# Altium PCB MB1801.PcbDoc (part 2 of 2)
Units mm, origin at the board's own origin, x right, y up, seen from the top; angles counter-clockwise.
Board outline 70.1 x 57.1 mm, 2 copper layers (Top Layer, Bottom Layer), stack 1.554 mm thick; 124 components, 115 nets, 557 pads, 485 vias.
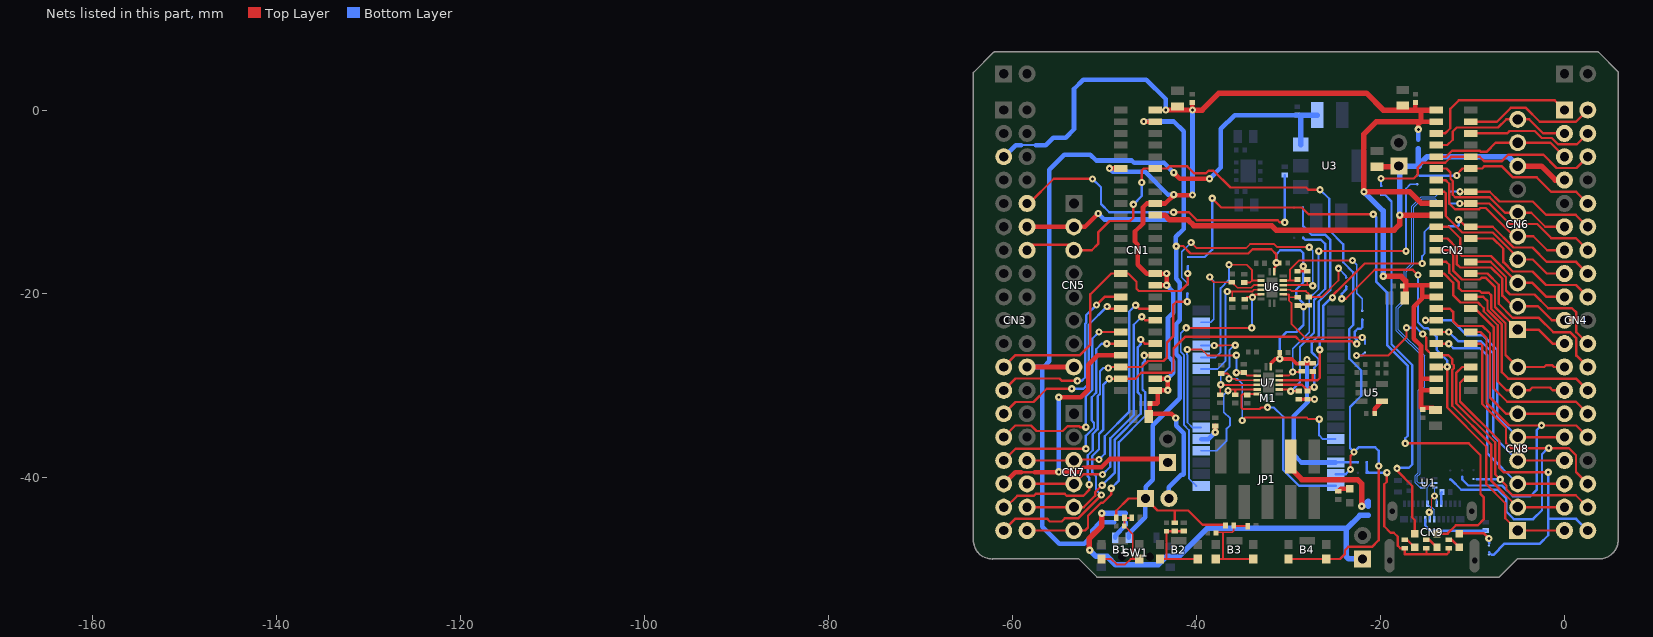
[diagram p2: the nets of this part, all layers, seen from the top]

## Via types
v1: diameter 0.8, hole 0.3, Top Layer to Bottom Layer, tented both sides, 485 vias

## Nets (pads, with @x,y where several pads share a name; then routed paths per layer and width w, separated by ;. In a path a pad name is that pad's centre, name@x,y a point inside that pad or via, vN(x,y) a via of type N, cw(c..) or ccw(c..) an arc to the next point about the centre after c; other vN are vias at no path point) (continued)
GPIO14: CN1.29 CN3.23 SB10.1 | length 31.1
  Top Layer w0.254: CN3.23@-60.96,-27.94 -59.67,-26.65 -52.68,-26.65 -51.537,-25.507 -51.537,-20.041 -49.276,-17.78 CN1.29@-48.225,-17.78 -47.422,-17.78 -46.533,-18.669 -46.533,-19.437 -46.285,-19.685 -41.732,-19.685 -40.97,-18.923 v1(-40.97,-17.78) v1@-40.97,-17.653
  Bottom Layer w0.254: v1(-40.97,-17.78) -40.97,-17.002 SB10.1@-40.931,-16.963
GPIO15/OSC32_IN: CN1.33 CN3.25 | length 21.1
  Top Layer w0.254: CN3.25@-60.96,-30.48 -59.665,-29.185 -54.89,-29.185 -54.625,-29.45 v1(-52.95,-29.45) ; v1(-50.88,-21.2) -50,-20.32 CN1.33@-48.225,-20.32
  Bottom Layer w0.254: v1(-52.95,-29.45) -52.49,-29.45 -52.104,-29.064 -52.104,-23.239 -52,-23.135 -52,-22.32 v1(-50.88,-21.2)
GPIO16/OSC32_OUT: CN1.35 CN3.27 | length 21.4
  Top Layer w0.254: CN3.27@-60.96,-33.02 -59.69,-31.75 -57.725,-31.75 -56.275,-30.3 v1(-53.575,-30.3) ; v1(-49.725,-21.361) -49.496,-21.59 CN1.35@-48.225,-21.59
  Bottom Layer w0.254: v1(-53.575,-30.3) -52.3,-30.3 -51.714,-29.714 -51.714,-23.35 v1(-49.725,-21.361)
GPIO17: CN1.36 CN3.32 CN7.3 | length 28.6
  Top Layer w0.254: CN3.32@-58.42,-38.1 CN7.3@-53.34,-38.1 -53.24,-38 v1(-50.6,-38) ; v1(-46.625,-21.225) -46.6,-21.225 -46.235,-21.59 CN1.36@-44.485,-21.59
  Bottom Layer w0.254: v1(-50.6,-38) -49.975,-37.375 -49.975,-35.475 -47.325,-32.825 -47.325,-21.925 v1(-46.625,-21.225)
GPIO18: CN1.38 CN3.34 CN7.4 | length 29.3
  Top Layer w0.254: CN3.34@-58.42,-40.64 CN7.4@-53.34,-40.64 -52.299,-39.599 -50.436,-39.599 -50.339,-39.501 -50.22,-39.383 v1@-50.183,-39.383 ; v1(-45.95,-22.475) -45.565,-22.86 CN1.38@-44.485,-22.86
  Bottom Layer w0.254: v1(-50.216,-39.624) -49.375,-38.783 -49.375,-35.7 -46.825,-33.15 -46.825,-23.35 v1(-45.95,-22.475)
GPIO19/OSC_IN: CN1.39 CN3.29 | length 23.3
  Top Layer w0.254: CN3.29@-60.96,-35.56 -59.7,-34.3 -57.981,-34.3 -57.382,-34.9 -54.534,-34.9 -54,-34.366 -52.759,-34.366 -52.65,-34.475 v1(-52.025,-34.475) ; v1(-50.605,-24.13) CN1.39@-48.225,-24.13
  Bottom Layer w0.254: v1(-52.025,-34.475) -52.025,-31.125 -51.333,-30.433 -51.333,-24.858 v1(-50.605,-24.13)
GPIO20/OSC_OUT: CN1.41 CN3.31 | length 23.9
  Top Layer w0.254: CN3.31@-60.96,-38.1 -59.685,-36.825 v1(-52.025,-36.825) ; v1(-49.75,-25.4) CN1.41@-48.225,-25.4
  Bottom Layer w0.254: v1(-52.025,-36.825) -52.025,-35.412 -51.148,-34.535 -51.148,-34.015 -51.4,-33.763 -51.4,-31.225 -50.902,-30.727 -50.902,-26.002 -50.3,-25.4 v1(-49.75,-25.4)
GPIO21: CN1.42 CN3.36 CN7.5 | length 29
  Top Layer w0.254: CN3.36@-58.42,-43.18 CN7.5@-53.34,-43.18 -52.273,-43.18 -51.029,-41.935 -51.029,-41.554 v1(-50.267,-40.792) ; v1(-46.075,-24.95) -45.625,-25.4 CN1.42@-44.485,-25.4
  Bottom Layer w0.254: v1(-50.267,-40.792) -48.875,-39.401 -48.875,-35.825 -46.075,-33.025 -46.075,-31.006 -46.375,-30.706 -46.375,-25.8 -46.075,-25.5 v1(-46.075,-24.95)
GPIO22: CN1.44 CN3.38 CN7.6 | length 29.7
  Top Layer w0.254: CN3.38@-58.42,-45.72 CN7.6@-53.34,-45.72 -52.121,-45.72 -51.791,-45.39 -51.791,-44.105 -50.383,-42.697 -50.165,-42.697 -49.276,-41.808 v1(-49.276,-41.123) ; v1(-45.675,-26.675) -45.68,-26.67 CN1.44@-44.485,-26.67
  Bottom Layer w0.254: v1(-49.276,-41.123) -48.438,-40.284 -48.438,-36.113 -45.575,-33.25 -45.575,-30.675 -45.875,-30.375 -45.875,-27.55 -45.625,-27.3 -45.625,-26.675 v1(-45.675,-26.675)
GPIO23: CN1.45 CN3.35 SB5.1 | length 40.6
  Top Layer w0.254: CN3.35@-60.96,-43.18 -60.73,-43.18 -59.5,-41.95 -57.706,-41.95 -57.488,-41.732 -54.337,-41.732 -54.119,-41.95 -52.325,-41.95 -51.675,-41.3 v1(-51.675,-40.725) ; v1(-49.6,-28.05) -49.575,-28.05 -49.465,-27.94 CN1.45@-48.225,-27.94 -45.949,-27.94 -45.288,-27.28 -43.586,-27.28 -43.205,-26.899 -43.205,-25.273 -42.545,-24.613 -42.545,-21.184 -42.215,-20.853 -41.275,-20.853 -40.996,-20.574 v1(-40.996,-20.828)
  Bottom Layer w0.254: v1(-51.675,-40.725) -51.675,-39.95 -51.825,-39.8 -51.825,-37.525 -51.283,-36.982 -51.283,-35.229 -50.75,-34.696 -50.75,-31.125 -50.495,-30.87 -50.495,-28.395 -50.15,-28.05 v1(-49.6,-28.05) ; v1(-40.996,-20.828) -40.996,-19.982 SB5.1@-40.979,-19.966
GPIO24: CN1.47 CN3.37 SB3.1 | length 60.1
  Top Layer w0.254: CN3.37@-60.96,-45.72 -59.665,-44.425 -56.261,-44.425 -55.956,-44.729 -54.661,-44.729 -54.331,-44.399 -52.883,-44.399 v1(-50.343,-41.859) ; v1@-49.525,-29.21 v1(-49.493,-29.21) CN1.47@-48.225,-29.21 -46.634,-29.21 -45.999,-28.575 -42.748,-28.575 -42.494,-28.321 -42.494,-25.933 -41.199,-24.638 -29.235,-24.638 -28.727,-25.146 -23.114,-25.146 -22.835,-25.425 v1(-22.581,-25.425)
  Bottom Layer w0.254: v1@-50.341,-41.859 v1(-50.343,-41.859) -50.343,-41.857 -50.925,-41.275 -50.925,-39.825 -51.35,-39.4 -51.35,-37.634 -50.595,-36.879 -50.595,-35.22 -50.125,-34.75 -50.125,-29.842 v1(-49.493,-29.21) ; v1(-22.581,-25.425) -22.581,-24.994 -22.784,-24.79 -22.784,-24.079 -22.479,-23.774 -22.149,-23.774 -21.98,-23.606 SB3.1@-21.98,-22.8
GPIO25: CN2.4 CN4.2 | length 14.5
  Top Layer w0.254: CN2.4@-10.195,-1.27 -7.341,-1.27 -5.842,0.229 -4.191,0.229 -2.687,-1.275 1.265,-1.275 CN4.2@2.54,0
GPIO26: CN2.5 CN4.1 | length 17.1
  Top Layer w0.254: CN2.5@-13.935,-2.54 -12.99,-2.54 -12.425,-1.975 -12.425,0.125 -11.5,1.05 -1.05,1.05 CN4.1@0,0
GPIO27: CN2.6 CN4.4 | length 13.9
  Top Layer w0.254: CN2.6@-10.195,-2.54 -6.223,-2.54 -5.958,-2.275 -3.237,-2.275 -2.462,-3.05 -1.375,-3.05 -0.7,-3.725 1.355,-3.725 CN4.4@2.54,-2.54
GPIO28: CN2.7 CN4.3 CN6.10 | length 16.2
  Top Layer w0.254: CN2.7@-13.935,-3.81 -12.735,-3.81 -12.15,-3.225 -12.15,-2.35 -11.7,-1.9 -7.209,-1.9 -6.325,-1.016 CN6.10@-5.08,-1.016 -3.835,-1.016 -2.311,-2.54 CN4.3@0,-2.54
GPIO29: CN2.9 CN4.5 CN6.9 | length 15.3
  Top Layer w0.254: CN2.9@-13.935,-5.08 -12.883,-5.08 -12.228,-4.425 -9.2,-4.425 -9.075,-4.55 -8.475,-4.55 -7.481,-3.556 CN6.9@-5.08,-3.556 -1.524,-3.556 CN4.5@0,-5.08
GPIO30: CN2.10 CN4.6 SB9.1 | length 26.3
  Top Layer w0.254: v1(-19.939,-7.442) -16.383,-7.442 -15.951,-7.01 -15.951,-6.248 -15.443,-5.74 -12.954,-5.74 -12.294,-5.08 CN2.10@-10.195,-5.08 -9.198,-5.08 -8.69,-5.588 -6.858,-5.588 -6.12,-4.85 -2.3,-4.85 -0.85,-6.3 1.32,-6.3 CN4.6@2.54,-5.08
  Bottom Layer w0.254: v1(-19.939,-7.442) -19.939,-8.255 SB9.1@-19.932,-8.262
GPIO31: CN2.11 CN4.11 CN6.6 | length 17.8
  Top Layer w0.254: CN2.11@-13.935,-6.35 -12.839,-6.35 -12.382,-6.807 -12.382,-7.481 -12.142,-7.721 -12.142,-9.219 -11.861,-9.5 -8.128,-9.5 -6.452,-11.176 CN6.6@-5.08,-11.176 -3.607,-11.176 -2.083,-12.7 CN4.11@0,-12.7
GPIO32: CN2.12 CN4.10 SB12.1 | length 20.5
  Top Layer w0.254: v1(-11.709,-7.112) -11.709,-6.985 -11.074,-6.35 CN2.12@-10.195,-6.35 -8.944,-6.35 -8.69,-6.096 -6.833,-6.096 -5.604,-7.325 -3,-7.325 -1.425,-8.9 1.28,-8.9 CN4.10@2.54,-10.16
  Bottom Layer w0.254: -15.748,-7.163 -11.76,-7.163 v1(-11.709,-7.112)
GPIO33: CN2.13 CN4.13 CN6.5 | length 18.5
  Top Layer w0.254: CN2.13@-13.935,-7.62 -12.929,-7.62 -12.522,-8.026 -12.522,-10.16 -11.882,-10.8 -9.3,-10.8 -9.15,-10.65 -8.55,-10.65 -5.484,-13.716 CN6.5@-5.08,-13.716 -3.384,-13.716 -1.86,-15.24 CN4.13@0,-15.24
GPIO34: CN2.15 CN4.15 CN6.4 | length 19.2
  Top Layer w0.254: CN2.15@-13.935,-8.89 -13.06,-8.89 -12.903,-9.047 -12.903,-11.522 -11.1,-13.325 -7.8,-13.325 -5.08,-16.045 CN6.4@-5.08,-16.256 -3.444,-16.256 -1.92,-17.78 CN4.15@0,-17.78
GPIO35: CN2.16 CN4.12 SB16.1 | length 16.6
  Top Layer w0.2: v1@-11.354,-8.873 -11.354,-8.89 CN2.16@-10.195,-8.89
  Top Layer w0.254: CN2.16@-10.195,-8.89 -8.128,-8.89 -7.068,-9.95 -3.436,-9.95 -1.986,-11.4 1.24,-11.4 CN4.12@2.54,-12.7
  Bottom Layer w0.2: SB16.1@-12.51,-8.87 v1(-11.354,-8.87)
GPIO36: CN2.18 CN4.14 SB14.1 | length 17.1
  Top Layer w0.254: v1(-11.379,-10.16) CN2.18@-10.195,-10.16 -8.18,-10.16 -5.94,-12.4 -2.967,-12.4 -1.442,-13.925 1.225,-13.925 CN4.14@2.54,-15.24
  Bottom Layer w0.254: SB14.1@-12.453,-10.16 v1(-11.379,-10.16)
GPIO37: CN2.21 CN4.17 CN6.3 | length 18.1
  Top Layer w0.254: CN2.21@-13.935,-12.7 -12.575,-12.7 -11.325,-13.95 -11.325,-15.7 -11.15,-15.875 -8,-15.875 -5.08,-18.795 -3.479,-18.796 -1.955,-20.32 CN4.17@0,-20.32
GPIO38: CN2.22 CN4.16 SB13.1 | length 18.2
  Top Layer w0.254: v1(-11.506,-11.913) -10.719,-12.7 CN2.22@-10.195,-12.7 -7.8,-12.7 -5.55,-14.95 -3.475,-14.95 -1.915,-16.51 1.27,-16.51 CN4.16@2.54,-17.78
  Bottom Layer w0.254: SB13.1@-12.555,-12.624 -11.608,-12.624 -11.506,-12.522 v1(-11.506,-11.913)
GPIO39: CN2.23 CN4.19 CN6.2 | length 19.7
  Top Layer w0.254: CN2.23@-13.935,-13.97 -12.73,-13.97 -11.725,-14.975 -11.725,-16.725 -11.325,-17.125 -7.975,-17.125 -6.75,-18.35 -6.75,-20.175 -5.589,-21.336 CN6.2@-5.08,-21.336 -2.889,-21.336 -1.365,-22.86 CN4.19@0,-22.86
GPIO40: CN2.24 CN4.18 | length 16.2
  Top Layer w0.254: CN2.24@-10.195,-13.97 -7.755,-13.97 -6.64,-15.085 -6.64,-16.535 -5.625,-17.55 -3.475,-17.55 -2,-19.025 1.245,-19.025 CN4.18@2.54,-20.32
GPIO41: CN2.25 CN4.21 CN6.1 | length 20.6
  Top Layer w0.254: CN2.25@-13.935,-15.24 -12.56,-15.24 -12.1,-15.7 -12.1,-17.45 -11.125,-18.425 -9.206,-18.425 -9.204,-18.423 -9.198,-18.423 -9.025,-18.25 -8.53,-18.25 -7.55,-19.23 -7.55,-21.406 CN6.1@-5.08,-23.876 -2.824,-23.876 -1.3,-25.4 CN4.21@0,-25.4
GPIO42: CN2.27 CN4.23 CN8.8 | length 22.6
  Top Layer w0.254: CN2.27@-13.935,-16.51 -12.84,-16.51 -12.525,-16.825 -12.525,-17.7 -11.475,-18.75 -11.475,-19.375 -11.175,-19.675 -9.206,-19.675 -9.018,-19.863 -8.237,-19.863 -7.975,-20.125 -7.975,-21.6 -6.4,-23.175 -6.4,-26.62 CN8.8@-5.08,-27.94 -2.184,-27.94 -1.981,-27.737 -1.346,-27.737 -1.143,-27.94 CN4.23@0,-27.94
GPIO43: CN2.28 CN4.22 | length 18.5
  Top Layer w0.254: CN2.28@-10.195,-16.51 -8.015,-16.51 -6.345,-18.18 -6.345,-19.63 -5.925,-20.05 -3.25,-20.05 -1.75,-21.55 0.825,-21.55 1.3,-22.025 1.3,-24.16 CN4.22@2.54,-25.4
GPIO44: CN2.29 CN4.25 CN8.7 | length 24
  Top Layer w0.254: CN2.29@-13.935,-17.78 -13.095,-17.78 -12.1,-18.775 -12.1,-20.117 -11.292,-20.925 -9.394,-20.925 -8.775,-21.544 -8.775,-21.88 -7.25,-23.405 -7.25,-29.5 -6.27,-30.48 CN8.7@-5.08,-30.48 -3.81,-30.48 -3.505,-30.175 -1.575,-30.175 -1.27,-30.48 CN4.25@0,-30.48
GPIO45: CN2.30 CN4.24 | length 19.2
  Top Layer w0.254: CN2.30@-10.195,-17.78 -8.37,-17.78 -7.15,-19 -7.15,-21.064 -5.614,-22.6 -2.775,-22.6 -1.225,-24.15 0.6,-24.15 1.3,-24.85 1.3,-26.7 CN4.24@2.54,-27.94
GPIO46: CN2.34 CN4.26 | length 20.5
  Top Layer w0.254: CN2.34@-10.195,-20.32 -8.83,-20.32 -8.37,-20.78 -8.37,-21.74 -6.8,-23.31 -6.8,-28.5 -6.1,-29.2 1.26,-29.2 CN4.26@2.54,-30.48
GPIO47: CN2.35 CN4.27 CN8.6 | length 23.3
  Top Layer w0.254: CN2.35@-13.935,-21.59 -12.46,-21.59 -12.1,-21.95 -12.1,-22.95 -11.575,-23.475 -8.9,-23.475 -8.1,-24.275 -8.1,-31.265 -6.345,-33.02 CN8.6@-5.08,-33.02 CN4.27@0,-33.02
GPIO48: CN2.36 CN4.28 | length 21.4
  Top Layer w0.254: CN2.36@-10.195,-21.59 -9.71,-21.59 -7.7,-23.6 -7.7,-30.25 -6.225,-31.725 1.245,-31.725 CN4.28@2.54,-33.02
GPIO49: CN2.37 CN4.29 CN8.5 | length 25.8
  Top Layer w0.254: v1(-15.1,-22.85) -15.09,-22.86 CN2.37@-13.935,-22.86 ; CN8.5@-5.08,-35.56 CN4.29@0,-35.56
  Bottom Layer w0.254: v1(-15.1,-22.85) -12.275,-22.85 -10.65,-24.475 -8.9,-24.475 -7.3,-26.075 -7.3,-33.34 CN8.5@-5.08,-35.56
GPIO50: CN2.39 CN4.31 CN8.4 | length 25
  Top Layer w0.254: CN2.39@-13.935,-24.13 v1(-12.57,-24.13) v1@-12.53,-24.13 ; CN8.4@-5.08,-38.1 CN4.31@0,-38.1
  Bottom Layer w0.254: v1(-12.57,-24.13) -11.575,-25.125 -9.1,-25.125 -7.75,-26.475 -7.75,-35.43 CN8.4@-5.08,-38.1
GPIO51: CN2.40 CN4.30 SB4.1 | length 38.3
  Top Layer w0.254: CN2.40@-10.195,-24.13 -9.125,-24.13 -8.475,-24.78 -8.475,-31.85 -6.025,-34.3 1.28,-34.3 CN4.30@2.54,-35.56
  Bottom Layer w0.254: -11.123,-39.853 SB4.1@-11.123,-40.147 -10.453,-40.818 -6.782,-40.818 -5.613,-41.986 -3.708,-41.986 -3.023,-41.3 -3.023,-34.823 v1(-2.489,-34.29)
GPIO52: CN2.41 CN4.33 CN8.3 | length 26.9
  Top Layer w0.254: CN2.41@-14.275,-25.4 CN2.41@-13.935,-25.4 v1(-12.575,-25.4) v1@-12.5,-25.4 ; CN8.3@-5.08,-40.64 CN4.33@0,-40.64
  Bottom Layer w0.254: v1(-12.575,-25.4) -12.075,-25.9 -9.175,-25.9 -8.375,-26.7 -8.375,-37.345 CN8.3@-5.08,-40.64
GPIO53: CN2.42 CN4.34 SB6.1 | length 44.9
  Top Layer w0.254: CN2.42@-10.195,-25.4 -9.105,-25.4 -8.925,-25.58 -8.925,-31.969 -6.35,-34.544 -6.35,-36.195 -5.77,-36.775 0.5,-36.775 1.25,-37.525 1.25,-39.35 CN4.34@2.54,-40.64
  Bottom Layer w0.254: SB6.1@-12.416,-40.168 -12.333,-40.168 -11.227,-41.275 -7.264,-41.275 -6.312,-42.228 -6.312,-43.675 -5.512,-44.475 -3.404,-44.475 -2.438,-43.51 -2.438,-37.414 -1.778,-36.754 v1(-1.702,-36.754)
GPIO54: CN2.43 CN4.35 CN8.2 SB8.1 | length 39.6
  Top Layer w0.254: v1(-22.606,-26.695) -19.152,-26.695 -17.17,-24.714 v1(-17.17,-23.665) ; v1(-15.418,-24.359) -15.011,-24.765 -15.011,-26.035 -14.376,-26.67 CN2.43@-13.935,-26.67 -12.598,-26.67 -12.2,-27.068 -12.2,-27.579 -12.038,-27.741 -12.038,-28.088 -12.2,-28.251 -12.2,-32.15 -7.975,-36.375 -7.975,-40.285 CN8.2@-5.08,-43.18 CN4.35@0,-43.18
  Bottom Layer w0.254: v1(-22.606,-26.695) -22.047,-26.695 -21.844,-26.492 ; v1(-17.17,-23.665) -16.112,-23.665 v1(-15.418,-24.359)
GPIO55: CN2.45 CN4.37 CN8.1 SB7.1 | length 49.8
  Top Layer w0.254: v1(-24.206,-20.523) -23.774,-20.523 -20.625,-17.374 -16.51,-17.374 -15.951,-17.932 v1(-15.926,-17.932) ; CN2.45@-13.935,-27.94 v1@-13.06,-27.94 ; v1(-12.751,-27.915) -12.751,-32.349 -8.5,-36.6 -8.5,-40.674 -6.425,-42.749 -6.425,-44.375 CN8.1@-5.08,-45.72 CN4.37@0,-45.72
  Bottom Layer w0.254: v1(-24.206,-20.523) -24.206,-19.99 -23.733,-19.516 SB7.1@-23.733,-19.179 ; v1(-15.926,-17.932) -15.926,-23.063 -15.265,-23.724 -14.834,-23.724 -13.892,-24.665 -13.892,-26.087 -12.751,-27.229 v1(-12.751,-27.915)
GPIO56: CN2.46 CN4.36 SB2.1 | length 29
  Top Layer w0.254: CN2.46@-10.195,-27.94 -11.115,-27.94 -11.775,-28.6 -11.775,-31.875 -7.525,-36.125 -7.525,-39.617 v1(-6.985,-40.157) -6.3,-40.842 -6.3,-41.225 -5.65,-41.875 1.235,-41.875 CN4.36@2.54,-43.18
  Bottom Layer w0.254: -9.557,-40.157 v1(-6.985,-40.157)
GPIO57: CN2.48 CN4.38 SB11.1 | length 37
  Top Layer w0.254: CN2.48@-10.195,-29.21 -10.91,-29.21 -11.35,-29.65 -11.35,-31.675 -7.088,-35.937 -7.088,-38.912 -6.624,-39.375 v1(-1.75,-39.375)
  Bottom Layer w0.254: -8.186,-48.09 -7.913,-48.363 -7.723,-48.363 -6.502,-47.142 -2.667,-47.142 -1.75,-46.225 -1.75,-44.45 ; v1(-1.75,-39.375) -1.75,-44.45 ; CN4.38@2.54,-45.72 1.27,-44.45 -1.75,-44.45
JTCLK/SWCLK: R29.1 SB15.2 U7.12 | length 27.4
  Top Layer w0.254: U7.12@-30.99,-29.88 -28.54,-29.88 R29.1@-27.991,-30.429 ; R29.1@-27.71,-30.542 -27.71,-30.124 -27.432,-30.124 -27.203,-29.896 v1(-27.203,-30.124)
  Bottom Layer w0.254: SB15.2@-28.431,-10.608 -28.431,-12.616 -27.47,-13.576 -25.971,-13.576 -25.476,-14.072 -25.476,-19.583 -26.721,-20.828 -26.721,-24.536 -27.457,-25.273 -27.457,-26.365 -26.721,-27.102 -26.721,-27.534 -27.203,-28.016 v1(-27.203,-30.124)
JTDI: R28.1 SB13.2 U7.13 | length 31.8
  Top Layer w0.254: U7.13@-30.99,-29.38 -27.374,-29.38 ; R28.1@-27.374,-28.426 -27.374,-29.38 ; v1@-26.594,-26.035 v1(-26.594,-26.06) -26.594,-29.134 -26.84,-29.38 -27.374,-29.38 ; v1(-25.209,-20.396) -25.209,-20.18 -24.105,-19.075 -21.717,-16.688 v1(-15.469,-16.688)
  Bottom Layer w0.2: v1(-15.469,-16.688) -15.469,-15.875 -15.215,-15.621 -15.215,-13.233 -14.605,-12.624 SB13.2@-13.53,-12.624
  Bottom Layer w0.254: v1(-26.594,-26.06) -26.594,-25.248 -26.238,-24.892 -26.238,-21.311 -25.324,-20.396 v1(-25.209,-20.396)
JTDO/SWO: R27.1 SB12.2 U7.14 | length 34.3
  Top Layer w0.2: U7.14@-30.99,-28.88 -29.943,-28.88 v1(-29.539,-28.476) R27.1@-28.855,-28.476 ; v1(-26.721,-15.342) v1(-17.221,-15.342)
  Bottom Layer w0.2: v1(-29.539,-28.476) -29.539,-25.946 -27.737,-24.143 -27.737,-20.472 -26.721,-19.456 v1(-26.721,-15.342) ; v1(-17.221,-15.342) -17.221,-8.533 -16.757,-8.069 SB12.2@-16.002,-8.069
JTMS/SWDIO: R30.1 SB17.2 U7.11 | length 22.4
  Top Layer w0.254: U7.11@-30.99,-30.38 -29.906,-30.38 -29.744,-30.542 R30.1@-28.889,-30.542
  Bottom Layer w0.254: v1(-29.743,-30.582) -28.753,-29.591 -28.753,-25.735 -27.232,-24.215 -27.232,-20.653 -26.01,-19.431 -26.01,-14.554 -26.467,-14.097 -28.215,-14.097 SB17.2@-28.411,-13.901
LD1: LD1.2 SB9.2 | length 40.9
  Top Layer w0.254: v1(-18.212,-38.964) -18.212,-39.192 -16.535,-40.869 -16.535,-44.298 -16.266,-44.567 LD1.2@-16.266,-46.05
  Bottom Layer w0.254: SB9.2@-19.932,-9.237 -19.49,-9.237 -18.796,-9.931 -18.796,-25.476 -16.535,-27.737 -16.535,-38.532 -16.891,-38.887 -18.288,-38.887 v1(-18.212,-38.964)
LD2: LD2.2 SB10.2 | length 74.9
  Top Layer w0.254: v1(-38.303,-9.601) -37.313,-10.592 -28.55,-10.592 -27.813,-11.328 v1(-20.777,-11.328) ; v1@-20.752,-11.328 v1@-20.726,-11.354 ; v1(-17.297,-36.246) -10.414,-36.246 -9.119,-37.541 -9.119,-41.758 -8.788,-42.088 -8.788,-44.526 -9.423,-45.161 -11.811,-45.161 -12.7,-46.05 LD2.2@-13.852,-46.05
  Bottom Layer w0.254: SB10.2@-40.931,-15.988 -39.102,-15.988 -38.303,-15.189 v1(-38.303,-9.601) ; v1(-20.777,-11.328) -20.447,-11.659 -20.447,-18.694 -19.253,-19.888 -19.253,-25.591 -17.018,-27.826 -17.018,-35.408 -17.297,-35.687 v1(-17.297,-36.246)
LD3: LD3.2 SB11.2 | length 4
  Top Layer w0.254: LD3.2@-11.424,-46.05 -11.373,-45.999 -8.795,-45.999 v1(-8.211,-46.584)
  Bottom Layer w0.254: v1(-8.211,-46.584) -8.211,-46.946 -8.186,-46.972 -8.186,-47.115
NetB1_2: B1.2 B1.4 C12.2 R2.1 R4.1 | length 10.3
  Top Layer w0.2: B1.4@-50.24,-48.822 -49.273,-48.822 -48.692,-49.403 -47.752,-49.403 -47.171,-48.822 -46.965,-48.822 ; R4.1@-46.99,-44.349 -47.821,-44.349 R2.1@-47.828,-44.343 -47.828,-45.221 -46.939,-46.11 -46.939,-48.797 -46.965,-48.822 ; B1.2@-46.14,-48.822 -46.965,-48.822
NetB2_2: B2.2 B2.4 C13.2 R3.1 R5.1 | length 9
  Top Layer w0.2: B2.4@-44.08,-48.822 -43.259,-48.822 B2.2@-39.98,-48.822
  Top Layer w0.254: C13.2@-43.317,-45.831 C13.2@-43.272,-45.786 R5.1@-41.408,-45.786 ; -43.259,-48.822 C13.2@-43.259,-45.831
NetB3_2: B3.2 B3.4 C14.2 R9.1 R10.1 | length 11.2
  Top Layer w0.2: B3.4@-37.921,-48.822 -37.16,-48.822 ; C14.2@-37.889,-45.984 -37.807,-45.902 -37.135,-45.902 ; R10.1@-34.439,-45.232 -35.889,-45.232 R9.1@-35.948,-45.173 -35.948,-45.753 -36.098,-45.902 -37.135,-45.902 ; B3.2@-33.821,-48.822 -37.16,-48.822 ; -37.16,-48.822 -37.135,-48.797 -37.135,-45.902
NetC27_2: C27.2 U5.4 | length 1.6
  Top Layer w0.5: C27.2@-20.632,-32.995 -20.632,-32.472 U5.4@-19.848,-31.688
NetCN3_10: CN3.10 R1.1 | length 37.8
  Top Layer w0.254: CN3.10@-58.42,-10.16 -58.211,-10.16 -55.519,-7.468 -51.283,-7.468 v1(-51.308,-7.493) ; v1@-42.875,-11.125 v1(-42.494,-11.125) ; v1@-42.52,-11.1 v1(-42.494,-11.125) ; v1(-30.397,-12.217) -30.937,-12.217 -31.166,-11.989 -39.964,-11.989 -40.828,-11.125 v1(-42.494,-11.125)
  Bottom Layer w0.254: v1(-51.308,-7.493) -50.394,-8.407 -50.394,-10.228 -49.496,-11.125 v1(-42.494,-11.125) ; v1(-30.397,-12.217) R1.1@-30.397,-7.073
NetCN9_A5: CN9.A5 R11.2 | length 1.3
  Bottom Layer w0.254: CN9.A5@-13.392,-42.818 -13.392,-41.607 R11.2@-13.315,-41.53
NetCN9_B5: CN9.B5 R12.2 | length 7.5
  Bottom Layer w0.254: CN9.B5@-15.142,-44.518 -15.142,-45.158 -14.55,-45.75 R12.2@-8.525,-45.75
NetJP1_8: JP1.8 SB21.2 | length 13.7
  Top Layer w0.6: JP1.8@-29.748,-37.671 -29.748,-38.984 -28.55,-40.183 -22.479,-40.183 -22.048,-40.614 v1(-22.048,-43.078)
  Bottom Layer w0.6: v1(-22.048,-43.078) -21.9,-43.078 -21.339,-42.517 SB21.2@-21.339,-43.085
NetLD1_1: LD1.1 R6.2 | length 1.4
  Top Layer w0.254: R6.2@-17.374,-46.735 -17.081,-46.735 LD1.1@-16.266,-47.55
NetLD2_1: LD2.1 R7.2 | length 1.5
  Top Layer w0.254: R7.2@-15.006,-46.734 -14.668,-46.734 LD2.1@-13.852,-47.55
NetLD3_1: LD3.1 R8.2 | length 1.5
  Top Layer w0.254: R8.2@-12.577,-46.735 -12.239,-46.735 LD3.1@-11.424,-47.55
NetLD4_1: LD4.1 R13.1 | length 1.4
  Top Layer w0.5: R13.1@-24.6,-41.452 -24.329,-41.181 LD4.1@-23.355,-41.181
NetM1_5: M1.5 R14.2 | length 2.5
  Top Layer w0.5: v1@-37.978,-35.022 R14.2@-37.978,-34.357
  Bottom Layer w0.5: M1.5@-39.498,-35.779 -38.726,-35.779 v1(-37.973,-35.027)
NetR6_1: R6.1 R7.1 R8.1 SB18.1 SB19.1 | length 20.1
  Top Layer w0.254: v1(-19.304,-39.421) -19.304,-40.411 -19.583,-40.691 -19.583,-45.263 -18.898,-45.949 -18.554,-45.949 -18.11,-46.392 -18.11,-47.371 -17.847,-47.635 R6.1@-17.374,-47.635 -17.374,-48.26 -17.323,-48.311 -14.935,-48.311 ; R7.1@-15.006,-47.634 -15.006,-48.24 -14.935,-48.311 ; R8.1@-12.577,-47.635 -12.577,-48.086 -12.802,-48.311 -14.935,-48.311
  Bottom Layer w0.254: SB18.1@-21.48,-38.278 SB19.1@-21.48,-39.446 ; -21.353,-39.319 SB19.1@-21.48,-39.446 ; v1@-19.304,-39.557 v1(-19.304,-39.421) -19.329,-39.446 SB19.1@-21.48,-39.446
NetSB22_2: SB22.2 SW1.3 | length 2.2
  Bottom Layer w0.5: SW1.3@-48.85,-46.509 -48.85,-46.284 -47.724,-45.158 SB22.2@-47.724,-44.815
NRST: B4.2 B4.4 CN1.12 CN3.14 CN5.3 M1.31 | length 99.4
  Top Layer w0.254: CN3.14@-58.42,-15.24 -57.81,-14.63 -53.95,-14.63 CN5.3@-53.34,-15.24 -51.384,-15.24 -50.698,-14.554 -50.698,-13.31 -49.464,-12.075 -47.226,-12.075 -46.863,-11.712 v1(-46.863,-10.262) ; v1(-45.95,-7.874) -45.95,-6.58 -45.72,-6.35 CN1.12@-44.485,-6.35 -43.155,-6.35 -42.926,-6.121 -41.021,-6.121 -40.259,-6.883 -38.964,-6.883 -38.684,-6.604 -38.151,-6.604 -36.322,-8.433 -28.067,-8.433 -27.838,-8.661 v1(-26.568,-8.661) ; B4.4@-29.996,-48.822 B4.2@-25.896,-48.822 -24.413,-48.822 -23.851,-48.26 -23.851,-47.854 -23.495,-47.498 -20.93,-47.498 -20.193,-46.761 v1@-20.193,-38.829 ; v1(-23.266,-39.091) -23.266,-37.617 -22.885,-37.236 v1(-22.885,-37.186)
  Bottom Layer w0.254: v1(-46.863,-10.262) -45.949,-9.347 -45.95,-9.346 v1(-45.95,-7.874) ; v1(-26.568,-8.661) -25.578,-9.652 -25.578,-13.081 -24.054,-14.605 -24.054,-16.561 -22.962,-17.653 -22.962,-23.368 -23.393,-23.8 -23.393,-27.026 -22.098,-28.321 -22.098,-31.064 -23.317,-32.283 -23.317,-36.754 v1(-22.885,-37.186) -22.377,-36.678 -20.574,-36.678 -20.193,-37.059 v1(-20.193,-38.71) ; M1.31@-24.858,-39.589 -23.79,-39.589 -23.292,-39.091 v1(-23.266,-39.091)
STLK_JCLK: M1.13 R25.1 U7.5 | length 14.1
  Top Layer w0.2: v1(-38.075,-25.603) -37.071,-25.603 -37.039,-25.572 v1(-35.784,-25.572) ; R25.1@-37.417,-30.942 v1@-37.417,-29.924 ; v1@-37.414,-29.88 U7.5@-33.39,-29.88
  Bottom Layer w0.2: M1.13@-39.498,-25.619 -38.091,-25.619 v1(-38.075,-25.603) ; v1(-37.363,-29.87) -37.363,-28.88 -36.398,-27.915 -36.398,-26.06 -35.954,-25.616 -35.784,-25.786 v1(-35.784,-25.572)
STLK_JTDI: M1.28 R24.1 U7.4 | length 22.5
  Top Layer w0.2: R24.1@-37.329,-28.651 -36.627,-28.651 -36.474,-28.804 v1(-36.474,-29.21) -35.865,-29.21 -35.695,-29.38 U7.4@-33.39,-29.38 ; v1(-35.027,-33.757) -34.684,-33.414 -28.029,-33.414 -27.838,-33.604 v1(-26.67,-33.604)
  Bottom Layer w0.2: v1(-36.474,-29.21) -35.56,-29.21 -35.027,-29.743 v1(-35.027,-33.757) ; v1(-26.67,-33.604) -26.67,-35.382 -26.273,-35.779 M1.28@-24.858,-35.779
STLK_JTDO: M1.6 R23.1 U7.3 | length 19.6
  Top Layer w0.2: v1(-41.021,-26.035) -39.446,-26.035 -38.808,-26.673 v1(-35.664,-26.673) ; v1(-35.664,-28.547) -35.66,-28.542 R23.1@-34.846,-28.542 -34.508,-28.88 U7.3@-33.39,-28.88
  Bottom Layer w0.2: v1(-41.021,-26.035) -41.021,-26.594 -40.98,-26.635 -40.98,-33.976 -40.446,-34.509 M1.6@-39.498,-34.509 ; v1(-35.664,-28.547) v1(-35.664,-26.673)
STLK_JTMS: M1.4 R26.1 U7.6 | length 13.8
  Top Layer w0.254: v1(-36.576,-30.505) -36.461,-30.391 -35.776,-30.391 -35.784,-30.399 -35.784,-30.776 R26.1@-35.584,-30.976 ; -35.584,-30.391 -35.954,-30.38 U7.6@-33.39,-30.38
  Bottom Layer w0.2: M1.4@-39.498,-37.049 -37.811,-37.049 -36.728,-35.966 -36.728,-34.639 -36.347,-34.258 -36.347,-33.528 -37.033,-32.842 -37.033,-30.963 v1(-36.576,-30.505)
STLK_SW_DIR: M1.32 R31.1 U7.7 | length 20.4
  Top Layer w0.254: U7.7@-33.39,-30.88 -34.929,-30.88 -35.103,-31.053 -35.103,-32.36 -34.95,-32.512 -33.147,-32.512 -32.969,-32.334 v1(-32.283,-32.334)
  Bottom Layer w0.254: v1(-32.283,-32.334) -31.598,-32.334 -30.582,-33.351 -30.582,-39.141 -28.864,-40.859 M1.32@-24.858,-40.859
STLK_VCP2_RX: M1.1 R18.1 U6.6 | length 30.7
  Top Layer w0.2: v1(-41.123,-23.69) v1(-33.985,-23.69) ; R18.1@-34.76,-20.559 -34.546,-20.345 v1(-33.909,-20.345) -33.605,-20.041 U6.6@-32.99,-20.041
  Bottom Layer w0.2: v1(-41.123,-23.69) -41.708,-24.276 -41.708,-26.288 -41.351,-26.645 -41.351,-34.265 -40.818,-34.798 -40.818,-40.081 -40.04,-40.859 M1.1@-39.98,-40.859 ; v1(-33.985,-23.69) -33.985,-20.422 v1(-33.909,-20.345)
STLK_VCP2_TX: M1.11 R17.1 U6.5 | length 15.3
  Top Layer w0.2: v1(-36.652,-19.736) -36.122,-19.736 ; R17.1@-36.122,-20.574 -36.122,-19.736 ; U6.5@-32.99,-19.541 -33.765,-19.541 -33.96,-19.736 -36.122,-19.736
  Bottom Layer w0.2: M1.11@-39.498,-28.159 -37.71,-28.159 -36.855,-27.305 -36.855,-19.939 v1(-36.652,-19.736) v1@-36.576,-19.66
T_VCP1_RX: M1.15 R16.1 U6.4 | length 12.5
  Top Layer w0.2: v1(-38.557,-18.161) -38.557,-18.285 -38.124,-18.718 R16.1@-36.158,-18.718 -35.547,-19.329 -34.061,-19.329 -33.773,-19.041 U6.4@-32.99,-19.041
  Bottom Layer w0.2: M1.15@-39.498,-23.079 -38.446,-23.079 -38.125,-22.758 -38.125,-18.593 v1(-38.557,-18.161)
T_VCP1_TX: M1.12 R15.1 U6.3 | length 18
  Top Layer w0.2: v1(-36.474,-16.815) -34.544,-16.815 -33.96,-17.399 -33.96,-18.541 ; R15.1@-34.796,-18.743 -34.162,-18.743 -33.96,-18.541 ; U6.3@-32.99,-18.541 -33.96,-18.541
  Bottom Layer w0.2: M1.12@-39.498,-26.889 -37.938,-26.889 -37.389,-26.34 -37.389,-19.355 -36.474,-18.44 v1(-36.474,-16.815)
USB_C_N: CN9.A7 CN9.B7 U1.5 | length 4.9
  Bottom Layer w0.12: CN9.B7@-14.142,-44.518 -14.142,-43.481 -14.444,-43.179 -14.532,-43.179 -14.892,-42.818 -14.892,-41.017 -14.425,-40.55 U1.5@-14.091,-40.55
USB_C_P: CN9.A6 CN9.B6 U1.6 | length 4.8
  Top Layer w0.12: v1@-14.707,-43.708 v1(-14.707,-43.739) -14.427,-43.459 -14.427,-42.266 v1(-14.122,-41.961) v1@-14.072,-41.91
  Bottom Layer w0.12: v1@-14.702,-43.743 -14.63,-43.815 -14.63,-44.506 CN9.B6@-14.642,-44.518 ; U1.6@-14.091,-41.05 -14.091,-41.929 v1(-14.122,-41.961) -14.122,-42.088 -13.892,-42.318 CN9.A6@-13.892,-42.818
USB_N: SB14.2 U1.2 | length 36.2
  Bottom Layer w0.12: U1.2@-15.391,-40.55 -15.838,-40.55 -15.977,-40.411 -15.977,-39.836 -15.693,-39.552 -15.693,-30.56 -15.196,-30.064 -15.196,-26.739 -18.055,-23.88 -18.055,-21.543 -17.196,-20.684 -17.196,-17.585 -16.358,-16.747 -16.358,-10.55 -15.469,-9.661 -14.029,-9.661 SB14.2@-13.479,-10.211
USB_P: SB16.2 U1.1 | length 37
  Bottom Layer w0.12: U1.1@-15.391,-41.05 -15.651,-41.05 -16.198,-40.503 -16.198,-39.744 -15.915,-39.46 -15.915,-30.469 -15.85,-30.404 -15.418,-29.972 -15.418,-26.831 -18.212,-24.037 -18.277,-23.972 -18.277,-21.452 -18.212,-21.387 -17.417,-20.592 -17.417,-17.494 -16.579,-16.655 -16.579,-10.458 -15.56,-9.44 -14.054,-9.44 SB16.2@-13.504,-8.89
V_TARGET: C29.2 C31.2 CN1.4 CN3.12 CN5.2 JP2.1 M1.30 R2.2 R3.2 R9.2 R19.2 R20.2 R21.2 R22.2 R27.2 R28.2 R29.2 R30.2 SB18.2 SW1.2 U6.16 U7.16 | length 145.9
  Top Layer w0.254: R2.2@-48.728,-44.343 -48.728,-43.571 -47.393,-42.237 JP2.1@-45.541,-42.237 -44.242,-43.536 -40.894,-43.536 -39.347,-45.083 -36.939,-45.083 R9.2@-36.848,-45.173 ; v1(-45.745,-1.245) v1@-45.72,-1.27 ; R3.2@-42.365,-44.871 -42.365,-43.61 ; v1(-42.215,-14.808) -42.189,-14.783 -41.453,-14.783 -40.64,-15.596 -34.366,-15.596 -33.909,-15.138 -31.877,-15.138 -31.318,-15.697 v1(-31.318,-16.612) ; U6.16@-31.54,-17.591 -31.54,-17.18 C29.2@-30.99,-16.63 ; R19.2@-29.021,-17.527 R20.2@-27.969,-17.528 ; -28.524,-17.501 -28.397,-17.374 v1(-28.397,-16.993)
  Top Layer w0.4: -31.864,-27.497 -31.439,-27.072 -29.639,-27.072 -29.11,-27.601 R28.2@-27.374,-27.601 ; v1(-30.96,-27.051) C31.2@-30.96,-26.362 ; R30.2@-28.889,-31.442 v1@-27.178,-31.442
  Top Layer w0.5: CN3.12@-58.42,-12.7 CN5.2@-53.34,-12.7 -52.121,-12.7 v1(-50.673,-11.252) ; v1@-45.72,-1.27 CN1.4@-44.485,-1.27
  Bottom Layer w0.254: v1(-31.318,-16.612) -31.318,-15.672 -30.886,-15.24 -28.702,-15.24 -28.397,-15.545 v1(-28.397,-16.993) -28.397,-18.745 -29.159,-19.507 -29.159,-20.244 -28.372,-21.031 v1(-28.372,-21.387) -28.372,-23.368 -29.134,-24.13 -30.219,-24.13 -30.96,-24.871 v1(-30.96,-27.051) ; M1.30@-24.858,-38.319 -24.817,-38.278 SB18.2@-22.455,-38.278
  Bottom Layer w0.4: -27.989,-31.445 v1(-27.989,-27.122) ; -27.864,-31.445 v1(-27.178,-31.445)
  Bottom Layer w0.5: v1(-50.673,-11.252) -50.698,-11.252 -50.051,-11.9 -41.427,-11.9 ; SW1.2@-47.35,-46.509 -47.35,-46.05 -45.566,-44.266 JP2.1@-45.566,-43.075 ; v1(-45.745,-1.245) -42.469,-1.245 -41.389,-2.324 -41.389,-11.9 -41.389,-12.941 -42.24,-13.792 v1@-42.24,-14.808 ; JP2.1@-45.541,-42.237 -45.541,-40.969 -44.78,-40.208 -44.78,-34.265 -41.834,-31.318 -41.834,-26.949 -42.215,-26.568 -42.215,-23.266 -41.808,-22.86 -41.808,-18.771 -42.215,-18.364 v1(-42.215,-14.808) ; -27.989,-31.445 -27.94,-31.396 -27.94,-31.77 -29.439,-33.269 -29.439,-37.465 -28.584,-38.319 M1.30@-24.858,-38.319
VBAT: CN1.43 CN3.33 CN14.1 | length 37.1
  Top Layer w0.3: -59.05,-39.375 -57.6,-39.375
  Top Layer w0.4: -53.746,-39.345 -52.807,-39.345 -52.299,-38.837 -51.765,-38.837
  Top Layer w0.5: CN3.33@-60.96,-40.64 -59.695,-39.375 -59.05,-39.375 ; -57.6,-39.375 v1@-55.055,-39.375 ; v1(-54.991,-39.345) -53.746,-39.345 ; v1(-54.975,-31.225) -52.575,-31.225 -51.75,-30.4 -51.75,-27.7 -50.72,-26.67 CN1.43@-48.225,-26.67 ; -51.765,-38.837 -50.328,-38.837 -49.429,-37.938 CN14.1@-43.186,-37.938
  Bottom Layer w0.5: v1@-54.975,-39.295 v1(-54.975,-31.225)
VCP1_RX: R20.1 SB5.2 U6.13 | length 27.4
  Top Layer w0.2: v1(-40.589,-14.402) -39.98,-15.011 -34.62,-15.011 -34.188,-14.58 -31.547,-14.58 -31.217,-14.91 v1(-27.737,-14.91) ; U6.13@-30.59,-19.041 -27.507,-19.041 -27.432,-19.117 -27.432,-19.38 -27.356,-19.304 v1(-27.356,-19.101) ; -27.969,-19.019 R20.1@-27.969,-18.428
  Bottom Layer w0.2: SB5.2@-40.979,-18.991 -40.979,-18.838 -41.611,-18.206 -41.611,-15.423 v1(-40.589,-14.402) ; v1@-27.762,-14.91 v1(-27.737,-14.91) -27.737,-14.935 -27.356,-15.316 v1(-27.356,-19.101)
VCP1_TX: R19.1 SB3.2 U6.14 | length 15.9
  Top Layer w0.2: U6.14@-30.59,-18.541 -29.845,-18.541 ; R19.1@-29.021,-18.541 -29.845,-18.541 ; v1(-23.038,-16.358) -28.854,-16.358 -29.845,-17.348 -29.845,-18.541
  Bottom Layer w0.2: v1(-23.038,-16.358) -22.581,-16.815 -22.581,-19.939 -21.98,-20.539 SB3.2@-21.98,-21.825
VCP2_RX: R21.1 SB7.2 U6.12 | length 9.9
  Top Layer w0.2: U6.12@-30.59,-19.541 -29.811,-19.541 -29.667,-19.685 -28.104,-19.685 -27.793,-19.997 R21.1@-27.793,-20.332 -26.378,-20.332 -24.562,-18.517 -24.562,-17.704 v1(-24.562,-17.221)
  Bottom Layer w0.2: v1(-24.562,-17.221) -23.733,-18.05 SB7.2@-23.733,-18.204
VCP2_TX: R22.1 SB8.2 U6.11 | length 14
  Top Layer w0.2: U6.11@-30.59,-20.041 -29.947,-20.041 -29.947,-20.357 ; R22.1@-29.015,-20.357 -29.947,-20.357 ; v1(-21.971,-24.74) -28.194,-24.74 -28.626,-24.308 -29.693,-23.241 -29.693,-20.98 -29.947,-20.726 -29.947,-20.357
  Bottom Layer w0.2: v1(-21.971,-24.74) -21.92,-24.74 -21.675,-24.985 SB8.2@-21.675,-25.379
VDD: C2.2 C3.2 C4.2 C5.2 C6.2 C7.2 C8.2 C9.2 C10.2 C11.2 CN1.2 CN1.11 CN1.18 CN1.30 CN1.32 CN1.48 CN1.50 CN2.1 CN2.3 CN2.17 CN2.31 CN2.33 CN2.47 CN2.49 CN3.5 JP2.2 SB1.1 | length 192.7
  Top Layer w0.3: -46.38,-15.57 -46.38,-14.63
  Top Layer w0.5: v1(-49.454,-6.35) CN1.11@-48.225,-6.35 ; -46.38,-15.57 -46.38,-16.815 -45.415,-17.78 CN1.30@-44.485,-17.78 v1(-43.256,-17.78) v1(-43.256,-19.05) CN1.32@-44.485,-19.05 ; -46.38,-14.63 -46.685,-14.326 -46.685,-13.208 -45.822,-12.344 -45.822,-10.566 -45.415,-10.16 CN1.18@-44.485,-10.16 -43.409,-10.16 -42.494,-9.246 v1(-40.437,-9.246) ; C3.2@-45.185,-33.303 C3.2@-45.064,-33.182 ; CN1.48@-44.485,-29.21 v1(-43.155,-29.21) -43.129,-29.235 v1(-43.129,-30.455) -44.459,-30.455 CN1.50@-44.485,-30.48 -44.22,-30.744 -44.22,-31.856 -44.269,-31.904 C8.2@-45.064,-31.904 C3.2@-45.064,-33.182 ; v1(-43.358,0) v1(-40.437,0) -40.464,0.027 C7.2@-40.464,0.818 ; v1(-42.266,-33.477) -42.72,-33.023 -44.906,-33.023 C3.2@-45.064,-33.182 ; -17.272,-19.05 -15.435,-19.05 ; -16.256,-0.025 -16.207,0.023 C9.2@-16.207,0.818 ; v1(-15.875,-2.108) -15.875,-1.549 -15.596,-1.27 ; -15.57,0 -15.596,-0.025 -15.596,-1.27 ; C6.2@-13.999,-32.622 -14.26,-32.36 -15.596,-32.36 -15.596,-30.455 ; CN2.49@-13.935,-30.48 -13.96,-30.455 -15.596,-30.455 ; CN2.47@-13.935,-29.21 -15.545,-29.21 -15.596,-29.261 ; CN2.33@-13.935,-20.32 -15.455,-20.32 ; CN2.31@-13.935,-19.05 -15.435,-19.05 ; CN2.3@-13.935,-1.27 -15.596,-1.27 ; -15.596,-30.455 -15.596,-29.261 ; -15.596,-29.261 -15.596,-25.629 -16.37,-24.855 -16.37,-21.373 -15.455,-20.459 -15.455,-20.32 ; -15.455,-20.32 -15.455,-19.07 -15.435,-19.05
  Top Layer w0.6: v1(-40.437,0) -39.395,0 -37.567,1.829 -21.539,1.829 -19.685,-0.025 -16.256,-0.025 -15.596,-0.025 ; v1(-19.71,-18.085) -17.755,-18.085 -17.272,-18.567 -17.272,-19.05 -17.272,-20.373 C5.2@-17.357,-20.457 ; -15.596,-1.27 -20.447,-1.27 -21.793,-2.616 v1(-21.793,-8.89) -16.815,-8.89 -15.545,-10.16 CN2.17@-13.935,-10.16 ; -15.57,0 CN2.1@-13.935,0
  Bottom Layer w0.254: -59.075,-3.81 -57.5,-3.81
  Bottom Layer w0.5: CN3.5@-60.96,-5.08 -60.935,-5.08 -59.665,-3.81 -59.075,-3.81 ; -57.5,-3.81 -56.388,-3.81 -55.575,-2.997 -54.229,-2.997 -53.321,-2.089 -53.321,2.279 -52.3,3.3 -45.464,3.3 -43.358,1.194 v1(-43.358,0) ; v1(-49.454,-6.35) -49.098,-6.706 -45.593,-6.706 -43.104,-9.195 v1(-42.469,-9.195) ; v1(-43.256,-19.05) -42.52,-19.787 -42.52,-22.022 -43.104,-22.606 -43.104,-26.746 -42.52,-27.33 -42.52,-28.575 v1(-43.155,-29.21) ; JP2.2@-43.001,-42.237 -43.001,-40.994 -41.668,-39.661 -41.423,-39.661 -41.377,-39.615 -41.377,-35.154 -42.215,-34.315 -42.215,-33.528 v1(-42.266,-33.477) ; v1(-40.437,-9.246) v1(-40.437,0) ; SB1.1@-15.878,-3.242 -15.878,-2.111 v1(-15.875,-2.108)
  Bottom Layer w0.6: v1(-21.793,-8.89) -19.71,-10.973 v1(-19.71,-18.085) v1@-19.634,-18.161
VDDA: C1.2 CN1.20 CN2.19 CN4.7 CN6.8 CN11.1 SB1.2 | length 61.6
  Top Layer w0.6: CN1.20@-44.485,-11.43 -43.434,-11.43 -42.926,-11.938 -40.919,-11.938 -40.284,-12.573 -31.826,-12.573 -31.344,-13.056 -18.517,-13.056 -17.912,-12.451 v1(-17.912,-11.425) -17.907,-11.43 CN2.19@-13.935,-11.43 ; C1.2@-20.387,-6.158 -18.078,-6.158 CN11.1@-18.013,-6.093 ; CN6.8@-5.08,-6.096 -2.504,-6.096 -0.98,-7.62 CN4.7@0,-7.62
  Bottom Layer w0.6: CN11.1@-18.015,-6.096 CN11.1@-18.013,-6.093 CN11.1@-18.01,-6.096 ; v1(-17.912,-11.425) -17.912,-6.194 CN11.1@-18.01,-6.096 ; SB1.2@-15.878,-4.217 -15.878,-6.017 -14.942,-5.08 -6.096,-5.08 CN6.8@-5.08,-6.096 ; -15.799,-6.096 CN11.1@-18.01,-6.096
Vext: CN10.1 SB20.1 SB21.1 SB22.1 | length 45.3
  Top Layer w0.6: v1(-51.613,-47.854) -51.638,-47.879 -51.638,-46.558 -50.292,-45.212 v1(-50.292,-43.84)
  Bottom Layer w0.6: v1(-51.613,-47.854) -50.927,-48.539 -49.708,-48.539 -48.793,-49.454 -44.171,-49.454 -43.256,-48.539 -41.885,-48.539 -38.811,-45.466 -23.724,-45.466 -23.724,-45.542 ; v1(-50.292,-43.84) -50.272,-43.861 SB20.1@-48.943,-43.861 ; SB20.1@-48.921,-43.84 SB22.1@-47.724,-43.84 ; CN10.1@-21.949,-48.805 -23.458,-48.805 -23.724,-48.539 -23.724,-45.542 ; SB21.1@-21.339,-44.06 -22.241,-44.06 -23.724,-45.542
VIN: C16.1 C18.2 CN3.24 CN5.8 SB20.2 U3.3 | length 94.9
  Top Layer w0.5: CN3.24@-58.42,-27.94 CN5.8@-53.34,-27.94 ; v1(-42.469,-6.807) -41.808,-7.468 v1(-38.583,-7.468) v1@-38.557,-7.468
  Bottom Layer w0.5: CN3.24@-58.42,-27.94 -56.642,-27.94 ; SB20.2@-48.943,-44.836 -50.449,-44.836 -51.333,-45.72 -51.333,-46.279 -52.197,-47.142 -54.94,-47.142 -56.769,-45.314 -56.769,-28.067 -56.642,-27.94 ; v1(-42.469,-6.807) -43.536,-5.74 -46.787,-5.74 -47.041,-5.486 -50.902,-5.486 -51.543,-4.845 -54.4,-4.845 -56.032,-6.477 -56.032,-27.33 -56.642,-27.94 ; v1(-38.583,-7.468) -37.363,-6.248 -37.363,-2.057 -35.857,-0.551 C18.2@-29.046,-0.551
  Bottom Layer w0.6: U3.3@-28.671,-3.757 -28.671,-0.551 ; -28.671,-0.546 C16.1@-26.896,-0.546
pads on no net: ?.1 B1.5 B2.5 B3.5 B4.5 CN5.1 CN9.A2 CN9.A3 CN9.A8 CN9.A10 CN9.A11 CN9.B2 CN9.B3 CN9.B8 CN9.B10 CN9.B11 M1.2 M1.3 M1.7 M1.9 M1.10 M1.14 M1.16 M1.17 M1.18 M1.19 M1.20 M1.21 M1.23 M1.25 SW1.NPTH1 SW1.NPTH2 U1.4 U4.3 U4.5
copper on no net:
  other v1: -24.867,-47.219

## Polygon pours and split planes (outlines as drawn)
no net on Top Solder (solid): -61.691,-47.229 -60.218,-47.229 -60.218,-48.372 -61.691,-48.372
no net on Bottom Solder (solid): -61.688,-47.234 -60.215,-47.234 -60.215,-48.377 -61.688,-48.377
GND on Top Layer "GND_L01_P002" (solid, remove dead copper, pour order 2): -65.1,7.747 6.883,7.747 6.883,-51.791 -65.1,-51.791
GND on Bottom Layer "GND_L02_P004" (solid, remove dead copper, pour order 4): -65.507,7.468 6.604,7.468 6.604,-52.07 -65.507,-52.07

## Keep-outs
Top Layer:
  lines w0.01: -61.646,-48.336 -61.646,-47.269 -60.249,-47.269 -60.249,-48.336 -61.646,-48.336
Bottom Layer:
  lines w0.01: -61.646,-48.336 -61.646,-47.269 -60.249,-47.269 -60.249,-48.336 -61.646,-48.336
Keep-Out Layer:
  lines w0.1: 3.781,-48.75 ccw(c3.794,-46.744) 5.8,-46.757 ; 3.794,-48.75 -5.15,-48.75 -7.15,-50.75 -50.775,-50.75 -52.775,-48.75 -62.2,-48.75 cw(c-62.263,-46.812) -64.2,-46.875 -64.2,4.075 -62,6.275 3.65,6.275 5.8,4.125 5.8,-46.744

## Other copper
Top Layer:
  text "1" at -61.519,-48.158 h1.2
Bottom Layer:
  text "2" at -60.425,-48.158 h1.2

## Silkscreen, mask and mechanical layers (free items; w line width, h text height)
Top Overlay:
  lines w0.1: -50.21,6.325 -50.21,-34.24 -39.599,-34.24 ; -33.655,-34.239 -23.012,-34.239 ; -20.193,-34.239 -15.011,-34.239 ; -13.004,-34.24 -8.21,-34.24 -8.21,6.325
  text "L" at -50.435,-39.139 h7.62
  text "MB1801A" at -6.621,-43.518 h2.5 r90
Bottom Overlay:
  text "L" at -7.065,0.704 h7.62
  text "I" at -45.692,-13.771 h7.62
  text "C" at -44.646,-20.308 h7.62
  text "H" at -45.614,-26.001 h7.62
M1-Board Shape:
  lines w0.1: -62.21,-48.768 cw(c-62.21,-46.768) -64.21,-46.768 -64.21,1.271 -64.21,4.048 -62.001,6.257 3.658,6.257 5.79,4.125 5.79,2.211 5.79,-46.743 cw(c3.79,-46.743) 3.79,-48.743 -5.131,-48.743 -7.131,-50.743 -50.786,-50.743 -52.761,-48.768 ; -62.21,-48.76 -52.789,-48.76
M3-Top Dimensions:
  lines w0.1: -60.96,0 9.144,0 ; -29.21,-37.998 -29.21,7.569
Drill Drawing:
  drawing of 187 lines, arcs and shapes, not listed
  text "Symbol" at -179.284,46.894 h2.16
  text "Count" at -170.822,46.894 h2.16
  text "Hole Size" at -162.037,46.894 h2.16
  text "Plated" at -146.487,46.894 h2.16
  text "Hole Type" at -139.059,46.894 h2.16
  text "Drill Layer Pair" at -128.244,46.894 h2.16
  text "Via/Pad" at -107.745,46.894 h2.16
  text "Pad Shape" at -98.884,46.894 h2.16
  text "Template" at -87.308,46.894 h2.16
  text "Description" at -61.31,46.894 h2.16
  text "Hole Tolerance (+)" at -49.684,46.894 h2.16
  text "Hole Tolerance (-)" at -31.605,46.894 h2.16
  text "Hole Length" at -14.012,46.894 h2.16
  text "Routed Path Length" at 1.558,46.894 h2.16
  text "2" at -170.822,43.166 h1.8
  text "0,60mm (23,62mil)" at -162.037,43.166 h1.8
  text "PTH" at -146.487,43.166 h1.8
  text "Slot" at -139.059,43.166 h1.8
  text "Top Layer - Bottom Layer" at -128.244,43.166 h1.8
  text "Pad" at -107.745,43.166 h1.8
  text "Rounded" at -98.884,43.166 h1.8
  text "r210_110h60_160r100m215_115" at -87.308,43.166 h1.8
  text "1,60mm (62,99mil)" at -14.012,43.166 h1.8
  text "1,00mm (39,37mil)" at 1.558,43.166 h1.8
  text "2" at -170.822,39.438 h1.8
  text "0,60mm (23,62mil)" at -162.037,39.438 h1.8
  text "PTH" at -146.487,39.438 h1.8
  text "Slot" at -139.059,39.438 h1.8
  text "Top Layer - Bottom Layer" at -128.244,39.438 h1.8
  text "Pad" at -107.745,39.438 h1.8
  text "Rounded" at -98.884,39.438 h1.8
  text "r260_110h60_210r100m265_115" at -87.308,39.438 h1.8
  text "2,10mm (82,68mil)" at -14.012,39.438 h1.8
  text "1,50mm (59,06mil)" at 1.558,39.438 h1.8
  text "2" at -170.822,35.71 h1.8
  text "0,90mm (35,43mil)" at -162.037,35.71 h1.8
  text "NPTH" at -146.487,35.71 h1.8
  text "Round" at -139.059,35.71 h1.8
  text "Top Layer - Bottom Layer" at -128.244,35.71 h1.8
  text "Pad" at -107.745,35.71 h1.8
  text "Rounded" at -98.884,35.71 h1.8
  text "c0hn90m95" at -87.308,35.71 h1.8
  text "-" at -14.012,35.71 h1.8
  text "-" at 1.558,35.71 h1.8
  text "32" at -170.822,31.982 h1.8
  text "1,10mm (43,31mil)" at -162.037,31.982 h1.8
  text "PTH" at -146.487,31.982 h1.8
  text "Round" at -139.059,31.982 h1.8
  text "Top Layer - Bottom Layer" at -128.244,31.982 h1.8
  text "Pad" at -107.745,31.982 h1.8
  text "Rounded" at -98.884,31.982 h1.8
  text "(Mixed)" at -87.308,31.982 h1.8
  text "-" at -14.012,31.982 h1.8
  text "-" at 1.558,31.982 h1.8
  text "88" at -170.822,28.253 h1.8
  text "1,00mm (39,37mil)" at -162.037,28.253 h1.8
  text "PTH" at -146.487,28.253 h1.8
  text "Round" at -139.059,28.253 h1.8
  text "Top Layer - Bottom Layer" at -128.244,28.253 h1.8
  text "Pad" at -107.745,28.253 h1.8
  text "Rounded" at -98.884,28.253 h1.8
  text "(Mixed)" at -87.308,28.253 h1.8
  text "-" at -14.012,28.253 h1.8
  text "-" at 1.558,28.253 h1.8
  text "485" at -170.822,24.525 h1.8
  text "0,30mm (11,81mil)" at -162.037,24.525 h1.8
  text "PTH" at -146.487,24.525 h1.8
  text "Round" at -139.059,24.525 h1.8
  text "Top Layer - Bottom Layer" at -128.244,24.525 h1.8
  text "Via" at -107.745,24.525 h1.8
  text "Rounded" at -98.884,24.525 h1.8
  text "v80h30m0mx0" at -87.308,24.525 h1.8
  text "-" at -14.012,24.525 h1.8
  text "-" at 1.558,24.525 h1.8
  text "611 Total" at -170.822,20.797 h1.8
  text "Slot definitions :" at -179.284,18.187 h1.8
  text "Routed Path Length" at -166.999,18.187 h1.8
  text "= Calculated from tool start centre position to tool end centre position." at -151.779,18.187 h1.8
  text "Hole Length" at -166.999,16.696 h1.8
  text "= Routed Path Length + Tool Size = Slot length as defined in the PCB layout" at -157.429,16.696 h1.8
  text "Layer" at -178.067,1.791 h1.52
  text "Name" at -171.689,1.791 h1.52
  text "Material" at -159.355,1.791 h1.52
  text "Thickness" at -148.272,1.791 h1.52
  text "Constant" at -139.168,1.791 h1.52
  text "Board Layer Stack" at -130.742,1.791 h1.52
  text "Top Overlay" at -171.689,-1.257 h1.52
  text "Top Solder" at -171.689,-4.305 h1.52
  text "Solder Resist" at -159.355,-4.305 h1.52
  text "0,018mm" at -148.272,-4.305 h1.52
  text "4,2" at -139.168,-4.305 h1.52
  text "1" at -178.067,-7.353 h1.52
  text "Top Layer" at -171.689,-7.353 h1.52
  text "Copper" at -159.355,-7.353 h1.52
  text "0,041mm" at -148.272,-7.353 h1.52
  text "Dielectric 1" at -171.689,-10.401 h1.52
  text "FR-4" at -159.355,-10.401 h1.52
  text "1,473mm" at -148.272,-10.401 h1.52
  text "4,4" at -139.168,-10.401 h1.52
  text "2" at -178.068,-13.449 h1.52
  text "Bottom Layer" at -171.689,-13.449 h1.52
  text "Copper" at -159.355,-13.449 h1.52
  text "0,041mm" at -148.272,-13.449 h1.52
  text "Bottom Solder" at -171.689,-16.497 h1.52
  text "Solder Resist" at -159.355,-16.497 h1.52
  text "0,018mm" at -148.272,-16.497 h1.52
  text "4,2" at -139.168,-16.497 h1.52
  text "Bottom Overlay" at -171.689,-19.545 h1.52

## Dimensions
5.79,4.125 to 3.658,6.257 on M2-Board Dimensions
3.79,-48.743 to 3.658,6.257 on M2-Board Dimensions
-7.131,-50.743 to -5.131,-48.743 on M2-Board Dimensions
-52.79,-48.81 to -64.21,-46.768 on M2-Board Dimensions
-50.786,-50.743 to -52.789,-48.76 on M2-Board Dimensions
-7.131,-50.743 to -50.786,-50.743 on M2-Board Dimensions
-5.11,-48.793 to 5.79,-46.743 on M2-Board Dimensions
-7.131,-50.743 to -5.131,-48.743 on M2-Board Dimensions
-7.131,-50.743 to 3.658,6.257 on M2-Board Dimensions
-64.21,-46.768 to 5.79,-46.743 on M2-Board Dimensions
-62.21,-48.76 to -60.96,-45.72 on M3-Top Dimensions
2.54,-45.72 to 5.79,-46.743 on M3-Top Dimensions
-60.96,-45.72 to -64.21,-46.768 on M3-Top Dimensions
-60.96,0 to -53.34,-10.16 on M3-Top Dimensions
-60.96,0 to -46.345,-15.24 on M3-Top Dimensions
-60.96,0 to -46.345,-15.24 on M3-Top Dimensions
-29.21,7.569 to -50.21,-34.24 on M3-Top Dimensions
-50.21,-34.24 to -8.21,-34.24 on M3-Top Dimensions
-46.345,-15.24 to -29.21,7.569 on M3-Top Dimensions
-46.345,-15.24 to -12.055,-15.24 on M3-Top Dimensions
-60.96,0 to -48.225,0 on M3-Top Dimensions
-48.225,0 to -13.935,0 on M3-Top Dimensions
-60.96,0 to -5.08,-1.016 on M3-Top Dimensions
-60.96,0 to -5.08,-27.94 on M3-Top Dimensions
-60.96,0 to -5.08,-1.016 on M3-Top Dimensions
-60.96,0 to -53.34,-33.02 on M3-Top Dimensions
-60.96,0 to -53.34,-10.16 on M3-Top Dimensions
0,0 to -60.96,0 on M3-Top Dimensions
